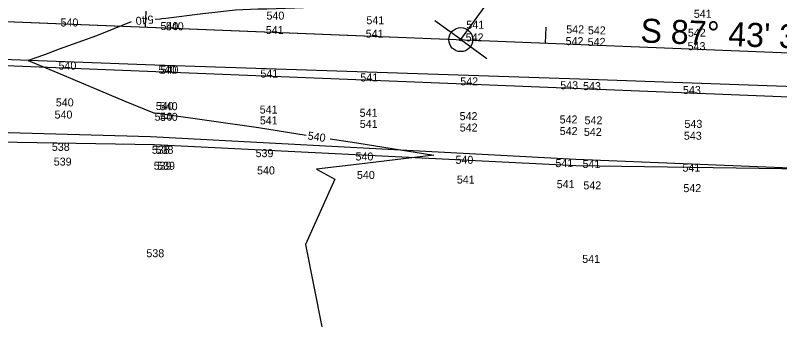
# Model space of a CAD drawing. Extents: x 1787461 to 1970323, y 938412 to 1118748.
# Drawn here: x 1968745.6 to 1968936.6, y 1117839.2 to 1117917.1 of the extents above; entities that cross this region are included whole.
import ezdxf

# ---------------------------------------------------------------- set-up
doc = ezdxf.new("R2010")
doc.units = 0
for name, color, linetype in [('Default', 7, 'Continuous'), ('RD_EX_DV_Prop', 7, 'Continuous'), ('RD_EX_Fence_Other', 7, 'Continuous'), ('RD_EX_Road', 7, 'Continuous'), ('RD_EX_VEG', 7, 'Continuous'), ('RD_HC_CL', 7, 'Continuous'), ('RD_HC_Data', 7, 'Continuous'), ('RD_HC_Data_Tic', 7, 'Continuous'), ('RD_PD_Final_TrvlWay', 7, 'Continuous'), ('RD_SMD_Locator', 7, 'Continuous')]:
    doc.layers.add(name, color=color, linetype=linetype)

msp = doc.modelspace()

# ---------------------------------------------------------------- linework, layer by layer
at = {"layer": 'Default'}
for points in [[(1968861.63, 1117922.57), (1968870.88, 1117920.42), (1968859.05, 1117920.15), (1968843.14, 1117919.79), (1968833.78, 1117919.48), (1968824.56, 1117919.24), (1968808.49, 1117918.66), (1968806.26, 1117918.6), (1968800.67, 1117918.38), (1968792.48, 1117917.44), (1968783.27, 1117916.27), (1968782.21, 1117916.19), (1968781.9, 1117916.17), (1968780.54, 1117916.07)], [(1968861.63, 1117922.57), (1968870.88, 1117920.42), (1968859.05, 1117920.15), (1968843.14, 1117919.79), (1968833.78, 1117919.48), (1968824.56, 1117919.24), (1968808.49, 1117918.66), (1968806.26, 1117918.6), (1968800.67, 1117918.38), (1968792.48, 1117917.44), (1968783.27, 1117916.27), (1968782.21, 1117916.19), (1968781.9, 1117916.17), (1968780.54, 1117916.07)], [(1968861.63, 1117922.57), (1968870.88, 1117920.42), (1968859.05, 1117920.15), (1968843.14, 1117919.79), (1968833.78, 1117919.48), (1968824.56, 1117919.24), (1968808.49, 1117918.66), (1968806.26, 1117918.6), (1968800.67, 1117918.38), (1968792.48, 1117917.44), (1968783.27, 1117916.27), (1968782.21, 1117916.19), (1968781.9, 1117916.17), (1968780.54, 1117916.07)], [(1968861.63, 1117922.57), (1968870.88, 1117920.42), (1968859.05, 1117920.15), (1968843.14, 1117919.79), (1968833.78, 1117919.48), (1968824.56, 1117919.24), (1968808.49, 1117918.66), (1968806.26, 1117918.6), (1968800.67, 1117918.38), (1968792.48, 1117917.44), (1968783.27, 1117916.27), (1968782.21, 1117916.19), (1968781.9, 1117916.17), (1968780.54, 1117916.07)], [(1968861.63, 1117922.57), (1968870.88, 1117920.42), (1968859.05, 1117920.15), (1968843.14, 1117919.79), (1968833.78, 1117919.48), (1968824.56, 1117919.24), (1968808.49, 1117918.66), (1968806.26, 1117918.6), (1968800.67, 1117918.38), (1968792.48, 1117917.44), (1968783.27, 1117916.27), (1968782.21, 1117916.19), (1968781.9, 1117916.17), (1968780.54, 1117916.07)], [(1968861.63, 1117922.57), (1968870.88, 1117920.42), (1968859.05, 1117920.15), (1968843.14, 1117919.79), (1968833.78, 1117919.48), (1968824.56, 1117919.24), (1968808.49, 1117918.66), (1968806.26, 1117918.6), (1968800.67, 1117918.38), (1968792.48, 1117917.44), (1968783.27, 1117916.27), (1968782.21, 1117916.19), (1968781.9, 1117916.17), (1968780.54, 1117916.07)], [(1968861.63, 1117922.57), (1968870.88, 1117920.42), (1968859.05, 1117920.15), (1968843.14, 1117919.79), (1968833.78, 1117919.48), (1968824.56, 1117919.24), (1968808.49, 1117918.66), (1968806.26, 1117918.6), (1968800.67, 1117918.38), (1968792.48, 1117917.44), (1968783.27, 1117916.27), (1968782.21, 1117916.19), (1968781.9, 1117916.17), (1968780.54, 1117916.07)], [(1968774.59, 1117915.49), (1968765.87, 1117912), (1968756.56, 1117908.61), (1968752.88, 1117907.21), (1968748.86, 1117905.82), (1968756.21, 1117902.74), (1968772.81, 1117895.7), (1968780.02, 1117892.8), (1968780.18, 1117892.75), (1968780.41, 1117892.72), (1968780.41, 1117892.72), (1968781.73, 1117892.58), (1968782.32, 1117892.49), (1968806.35, 1117889), (1968818.33, 1117887.13)], [(1968774.59, 1117915.49), (1968765.87, 1117912), (1968756.56, 1117908.61), (1968752.88, 1117907.21), (1968748.86, 1117905.82), (1968756.21, 1117902.74), (1968772.81, 1117895.7), (1968780.02, 1117892.8), (1968780.18, 1117892.75), (1968780.41, 1117892.72), (1968780.41, 1117892.72), (1968781.73, 1117892.58), (1968782.32, 1117892.49), (1968806.35, 1117889), (1968818.33, 1117887.13)], [(1968774.59, 1117915.49), (1968765.87, 1117912), (1968756.56, 1117908.61), (1968752.88, 1117907.21), (1968748.86, 1117905.82), (1968756.21, 1117902.74), (1968772.81, 1117895.7), (1968780.02, 1117892.8), (1968780.18, 1117892.75), (1968780.41, 1117892.72), (1968780.41, 1117892.72), (1968781.73, 1117892.58), (1968782.32, 1117892.49), (1968806.35, 1117889), (1968818.33, 1117887.13)], [(1968774.59, 1117915.49), (1968765.87, 1117912), (1968756.56, 1117908.61), (1968752.88, 1117907.21), (1968748.86, 1117905.82), (1968756.21, 1117902.74), (1968772.81, 1117895.7), (1968780.02, 1117892.8), (1968780.18, 1117892.75), (1968780.41, 1117892.72), (1968780.41, 1117892.72), (1968781.73, 1117892.58), (1968782.32, 1117892.49), (1968806.35, 1117889), (1968818.33, 1117887.13)], [(1968774.59, 1117915.49), (1968765.87, 1117912), (1968756.56, 1117908.61), (1968752.88, 1117907.21), (1968748.86, 1117905.82), (1968756.21, 1117902.74), (1968772.81, 1117895.7), (1968780.02, 1117892.8), (1968780.18, 1117892.75), (1968780.41, 1117892.72), (1968780.41, 1117892.72), (1968781.73, 1117892.58), (1968782.32, 1117892.49), (1968806.35, 1117889), (1968818.33, 1117887.13)], [(1968774.59, 1117915.49), (1968765.87, 1117912), (1968756.56, 1117908.61), (1968752.88, 1117907.21), (1968748.86, 1117905.82), (1968756.21, 1117902.74), (1968772.81, 1117895.7), (1968780.02, 1117892.8), (1968780.18, 1117892.75), (1968780.41, 1117892.72), (1968780.41, 1117892.72), (1968781.73, 1117892.58), (1968782.32, 1117892.49), (1968806.35, 1117889), (1968818.33, 1117887.13)], [(1968774.59, 1117915.49), (1968765.87, 1117912), (1968756.56, 1117908.61), (1968752.88, 1117907.21), (1968748.86, 1117905.82), (1968756.21, 1117902.74), (1968772.81, 1117895.7), (1968780.02, 1117892.8), (1968780.18, 1117892.75), (1968780.41, 1117892.72), (1968780.41, 1117892.72), (1968781.73, 1117892.58), (1968782.32, 1117892.49), (1968806.35, 1117889), (1968818.33, 1117887.13)], [(1968824.27, 1117886.23), (1968830.95, 1117885.24), (1968850.21, 1117882.14), (1968830.86, 1117879.75), (1968820.86, 1117878.63), (1968825.5, 1117876.13), (1968818.12, 1117859.75), (1968822.25, 1117839.22)], [(1968824.27, 1117886.23), (1968830.95, 1117885.24), (1968850.21, 1117882.14), (1968830.86, 1117879.75), (1968820.86, 1117878.63), (1968825.5, 1117876.13), (1968818.12, 1117859.75), (1968822.25, 1117839.22)], [(1968824.27, 1117886.23), (1968830.95, 1117885.24), (1968850.21, 1117882.14), (1968830.86, 1117879.75), (1968820.86, 1117878.63), (1968825.5, 1117876.13), (1968818.12, 1117859.75), (1968822.25, 1117839.22)], [(1968824.27, 1117886.23), (1968830.95, 1117885.24), (1968850.21, 1117882.14), (1968830.86, 1117879.75), (1968820.86, 1117878.63), (1968825.5, 1117876.13), (1968818.12, 1117859.75), (1968822.25, 1117839.22)], [(1968824.27, 1117886.23), (1968830.95, 1117885.24), (1968850.21, 1117882.14), (1968830.86, 1117879.75), (1968820.86, 1117878.63), (1968825.5, 1117876.13), (1968818.12, 1117859.75), (1968822.25, 1117839.22)], [(1968824.27, 1117886.23), (1968830.95, 1117885.24), (1968850.21, 1117882.14), (1968830.86, 1117879.75), (1968820.86, 1117878.63), (1968825.5, 1117876.13), (1968818.12, 1117859.75), (1968822.25, 1117839.22)], [(1968824.27, 1117886.23), (1968830.95, 1117885.24), (1968850.21, 1117882.14), (1968830.86, 1117879.75), (1968820.86, 1117878.63), (1968825.5, 1117876.13), (1968818.12, 1117859.75), (1968822.25, 1117839.22)]]:
    msp.add_lwpolyline(points, dxfattribs=at)
at = {"layer": 'RD_EX_DV_Prop'}
msp.add_line((1968370.12, 1117930.34), (1969277.79, 1117894.3), dxfattribs=at)
at = {"layer": 'RD_EX_Fence_Other'}
msp.add_lwpolyline([(1968579.94, 1117894.82), (1968678.66, 1117889.64), (1968779.4, 1117886.8), (1968885.65, 1117881.12), (1968982.76, 1117877.17), (1969084.96, 1117872.96), (1969186.26, 1117869.55), (1969289.22, 1117863.98)], dxfattribs=at)
at = {"layer": 'RD_EX_Road'}
msp.add_lwpolyline([(1968526.59, 1117915.77), (1968679.57, 1117908.43), (1968780.48, 1117904.73), (1968886.63, 1117901.2), (1968987.42, 1117897.59), (1969088.87, 1117892.19), (1969188.08, 1117888.4), (1969281.71, 1117884.78)], dxfattribs=at)
at = {"layer": 'RD_EX_VEG'}
msp.add_lwpolyline([(1968580.4, 1117892.39), (1968677.7, 1117886.58), (1968780.39, 1117884.76), (1968885.66, 1117879.53), (1968982.9, 1117878.1), (1969085.82, 1117874.51), (1969187.45, 1117870.95), (1969289.3, 1117866.04)], dxfattribs=at)
at = {"layer": 'RD_HC_CL'}
for p, q in [((1968856.94, 1117911.01), (1968968.89, 1118065.53)), ((1968119.1, 1117940.3), (1969277.79, 1117894.3))]:
    msp.add_line(p, q, dxfattribs=at)
at = {"layer": 'RD_HC_Data'}
for radius in [3, 0.282]:
    msp.add_circle((1968856.94, 1117911.01), radius, dxfattribs=at)
at = {"layer": 'RD_HC_Data_Tic'}
for p, q in [((1968778.18, 1117914.14), (1968778.34, 1117918.14)), ((1968856.94, 1117911.01), (1968850.47, 1117915.71)), ((1968878.1, 1117910.17), (1968878.26, 1117914.17)), ((1968856.94, 1117911.01), (1968863.42, 1117906.32))]:
    msp.add_line(p, q, dxfattribs=at)
at = {"layer": 'RD_PD_Final_TrvlWay'}
msp.add_line((1968477.98, 1117915.05), (1969277.35, 1117883.31), dxfattribs=at)
at = {"layer": 'RD_SMD_Locator'}
msp.add_circle((1968856.94, 1117911.01), 0.001, dxfattribs=at)

# ---------------------------------------------------------------- texts
at = {"layer": 'Default'}
for s, p in [('540', (1968808.38, 1117916.02)), ('541', (1968915.17, 1117916.47)), ('540', (1968756.91, 1117914.31)), ('541', (1968833.35, 1117914.87)), ('540', (1968781.89, 1117913.41)), ('540', (1968783.23, 1117913.36)), ('541', (1968808.21, 1117912.43)), ('541', (1968858.32, 1117913.73)), ('542', (1968883.29, 1117912.58)), ('542', (1968888.7, 1117912.33)), ('541', (1968833.18, 1117911.5)), ('542', (1968858.16, 1117910.57)), ('542', (1968913.69, 1117911.76)), ('542', (1968883.14, 1117909.64)), ('542', (1968888.64, 1117909.44)), ('543', (1968913.61, 1117908.38)), ('540', (1968756.41, 1117903.52)), ('540', (1968781.39, 1117902.53)), ('540', (1968781.89, 1117902.51)), ('541', (1968806.86, 1117901.53)), ('541', (1968831.84, 1117900.56)), ('542', (1968856.81, 1117899.58)), ('543', (1968881.79, 1117898.61)), ('543', (1968887.49, 1117898.39)), ('543', (1968912.46, 1117897.41)), ('540', (1968755.74, 1117894.32)), ('540', (1968780.72, 1117893.41)), ('540', (1968781.71, 1117893.37)), ('540', (1968755.42, 1117891.27)), ('541', (1968806.69, 1117892.54)), ('541', (1968831.67, 1117891.71)), ('540', (1968780.41, 1117890.74)), ('540', (1968781.74, 1117890.71)), ('541', (1968806.72, 1117889.82)), ('542', (1968856.65, 1117890.88)), ('542', (1968881.64, 1117890.05)), ('542', (1968887.86, 1117889.84)), ('541', (1968831.7, 1117888.93)), ('542', (1968856.68, 1117888.04)), ('542', (1968881.66, 1117887.15)), ('543', (1968912.83, 1117888.95)), ('542', (1968887.7, 1117886.94)), ('543', (1968912.68, 1117885.98)), ('538', (1968754.74, 1117883.2)), ('538', (1968779.73, 1117882.47)), ('538', (1968780.67, 1117882.45)), ('539', (1968805.65, 1117881.62)), ('539', (1968755.22, 1117879.51)), ('540', (1968830.63, 1117880.79)), ('540', (1968855.61, 1117879.96)), ('539', (1968780.2, 1117878.49)), ('539', (1968781.05, 1117878.46)), ('541', (1968880.59, 1117879.13)), ('541', (1968887.36, 1117878.9)), ('541', (1968912.33, 1117878)), ('540', (1968806.02, 1117877.31)), ('540', (1968830.98, 1117876.17)), ('541', (1968855.95, 1117875.02)), ('541', (1968880.92, 1117873.87)), ('542', (1968887.57, 1117873.57)), ('542', (1968912.56, 1117872.88)), ('538', (1968778.37, 1117856.59)), ('541', (1968887.28, 1117855.17))]:
    msp.add_text(s, height=2, dxfattribs=at).set_placement(p)
for rotation, p in [(185.5152, (1968780.05, 1117917.09)), (185.5152, (1968780.05, 1117917.09)), (185.5152, (1968780.05, 1117917.09)), (185.5152, (1968780.05, 1117917.09)), (185.5152, (1968780.05, 1117917.09)), (185.5152, (1968780.05, 1117917.09)), (185.5152, (1968780.05, 1117917.09)), (351.4228, (1968818.57, 1117886.07)), (351.4228, (1968818.57, 1117886.07)), (351.4228, (1968818.57, 1117886.07)), (351.4228, (1968818.57, 1117886.07)), (351.4228, (1968818.57, 1117886.07)), (351.4228, (1968818.57, 1117886.07)), (351.4228, (1968818.57, 1117886.07))]:
    msp.add_text('540', height=2, rotation=rotation, dxfattribs=at).set_placement(p)
at = {"layer": 'RD_HC_Data'}
msp.add_text('S 87%%D 43\' 36" E', height=6, rotation=357.7266, dxfattribs=at).set_placement((1968901.76, 1117910.33))

doc.saveas('drawing.dxf')
